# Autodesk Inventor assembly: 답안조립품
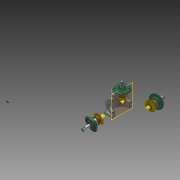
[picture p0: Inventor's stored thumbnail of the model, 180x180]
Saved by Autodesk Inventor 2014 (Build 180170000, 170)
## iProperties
Created: 2015-10
Part Number: 답안조립품
Document SubType Name: Assembly
Designer: 시험용
Author: 시험용
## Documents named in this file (14)
- C:\Users\시험용\Desktop\451007V1013\답안조립품.iam
- C:\Users\시험용\Desktop\451007V1013\M4.ipt
- C:\Users\시험용\Desktop\451007V1013\메인 베벨기어.ipt
- C:\Users\시험용\Desktop\451007V1013\메인 축.ipt
- 메인 축.ipt
- C:\Users\시험용\Desktop\451007V1013\베어링 6203.ipt
- C:\Users\시험용\Desktop\451007V1013\본체.ipt
- C:\Users\시험용\Desktop\451007V1013\서브 베벨기어.ipt
- C:\Users\시험용\Desktop\451007V1013\서브 축.ipt
- 서브 축.ipt
- C:\Users\시험용\Desktop\451007V1013\오일실.ipt
- C:\Users\시험용\Desktop\451007V1013\커버.ipt
- C:\Users\시험용\Desktop\451007V1013\키 4x4.ipt
- C:\Users\시험용\Desktop\451007V1013\키 5x5.ipt
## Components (1 placed, 1 different names)
1. M4:1
